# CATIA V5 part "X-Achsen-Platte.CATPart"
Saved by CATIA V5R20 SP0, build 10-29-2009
Part number: X-Achsen-Platte
Bounding box of the stored display mesh (mm): x -35 to 155, y -1 to 241, z 0 to 6
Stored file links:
  C:\Users\Andi\Desktop\Plasma\X-Achsen-Platte.CATPart
  C:\Program Files\Dassault Systemes\B20\win_b64\reffiles\standard\MetricThickPitch.txt
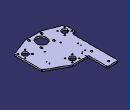
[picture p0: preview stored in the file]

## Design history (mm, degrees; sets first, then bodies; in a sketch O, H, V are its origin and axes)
Body1 (main body)
  Sketch1 on xy-plane, origin (0, 0, 0), H (1, 0, 0), V (0, 1, 0)
    construction circle A1 centre (-15, 44) radius 24
    point P1 (-15, 44)
    construction circle A2 centre (-15, 44) radius 19.95
    construction circle A3 centre (135, 44) radius 19.95
    point P2 (135, 44)
    construction circle A4 centre (135, 44) radius 24
    construction line L1 (-20, 136) -> (20, 136)
    construction line L2 (20, 136) -> (20, 241)
    construction line L3 (26.8489, 241) -> (-20, 241)
    construction line L4 (-20, 241) -> (-20, 136)
    point P5 (20, 241)
    line L5 (154.4846, 127.8747) -> (80.4846, 168.8747)
    line L6 (-20, 74) -> (-20, 238)
    circle A5 centre (0, 226) radius 4.1
    point P7 (0, 226)
    circle A6 centre (0, 161) radius 4.1
    point P8 (0, 161)
    circle A7 centre (-15, 44) radius 11
    circle A8 centre (135, 44) radius 11
    line L7 (-34.3676, 24.07) -> (28.1618, -0.6498)
    line L8 (17, 241) -> (-17, 241)
    circle A9 centre (60, 148) radius 11
    point P9 (60, 148)
    construction circle A10 centre (60, 148) radius 19.95
    construction circle A11 centre (60, 148) radius 24
    arc A12 centre (-17, 238) radius 3 from (-20, 238) to (-17, 241) cw
    construction line L9 (31, 62) -> (89, 62)
    construction line L10 (89, 62) -> (89, 0)
    construction line L11 (89, 0) -> (31, 0)
    construction line L12 (31, 0) -> (31, 62)
    construction line L13 (60, 29) -> (60, 33)
    point P17 (60, 29)
    point P18 (60, 33)
    line L14 (40.9, 29) -> (40.9, 33)
    line L15 (79.1, 33) -> (79.1, 29)
    arc A13 centre (60, 33) radius 19.1 from (40.9, 33) to (79.1, 33) cw
    arc A14 centre (60, 29) radius 19.1 from (79.1, 29) to (40.9, 29) cw
    construction line L16 (60, 148) -> (60, -15.4026)
    construction line L17 (-35.7345, 68) -> (137.8974, 68)
    construction line L18 (26.7433, 124) -> (71.6496, 124)
    point P27 (71.6496, 124)
    line L19 (91.8382, -0.6498) -> (154.3676, 24.07)
    line L20 (30, -1) -> (90, -1)
    arc A15 centre (30, 4) radius 5 from (30, -1) to (28.1618, -0.6498) cw
    point P30 (30, 4)
    arc A16 centre (90, 4) radius 5 from (91.8382, -0.6498) to (90, -1) cw
    point P33 (90, 4)
    arc A17 centre (-30, 74) radius 10 from (-20, 74) to (-30, 64) cw
    point P36 (26.8489, 241)
    line L21 (155, 127) -> (155, 25)
    line L22 (-35, 25) -> (-35, 63)
    line L23 (-34, 64) -> (-30, 64)
    arc A18 centre (-34, 63) radius 1 from (-35, 63) to (-34, 64) cw
    point P40 (-34, 63)
    arc A19 centre (-34, 25) radius 1 from (-34.3676, 24.07) to (-35, 25) cw
    point P43 (-34, 25)
    arc A20 centre (154, 25) radius 1 from (154.3676, 24.07) to (155, 25) ccw
    arc A21 centre (154, 127) radius 1 from (154.4846, 127.8747) to (155, 127) cw
    point P49 (154, 127)
    construction line L24 (80, 168) -> (80, 128)
    construction line L25 (80, 128) -> (40, 128)
    construction line L26 (40, 128) -> (40, 168)
    line L27 (20, 238) -> (20, 172)
    arc A22 centre (17, 238) radius 3 from (17, 241) to (20, 238) cw
    construction line L28 (40, 168) -> (80, 168)
    line L29 (80, 169) -> (23, 169)
    arc A23 centre (23, 172) radius 3 from (20, 172) to (23, 169) ccw
    arc A24 centre (80, 168) radius 1 from (80.4846, 168.8747) to (80, 169) ccw
    point P62 (80, 168)
    radius A2 = 19.95
    radius A1 = 24
    radius A5 = 4.1
    radius A6 = 4.1
    distance P8 L1 = 25
    radius A7 = 11
    radius A8 = 11 {= Sketch1.radius(A7)}
    distance P2 P1 = 150
    distance P7 L8 = 15
    radius A9 = 11 {= Sketch1.radius(A7)}
    radius A10 = 19.95 {= Sketch1.radius(A2)}
    radius A11 = 24 {= Sketch1.radius(A1)}
    length L2 = 105
    radius A12 = 3
    distance L9 L11 = 62
    distance L10 L12 = 58
    distance L13 L14 = 19.1
    distance P17 L11 = 29
    distance P18 L9 = 29 {= Sketch1.distance(P17 L11)}
    distance P27 L17 = 56
    distance L17 L9 = 6
    radius A15 = 5
    distance P33 P30 = 60
    distance L16 V = 60
    radius A17 = 10
    distance L11 L20 = 1
    distance L2 L6 = 40
    distance L22 P1 = 20
    radius A18 = 1
    radius A19 = 1 {= Sketch1.radius(A18)}
    distance L23 P1 = 20
    radius A20 = 1 {= Sketch1.radius(A18)}
    distance P40 P43 = 38
    distance L24 L26 = 40
    radius A22 = 3 {= Sketch1.radius(A12)}
    distance L1 L18 = 12
    distance L25 L28 = 40
    radius A23 = 3
    radius A24 = 1
    distance P62 L27 = 60
    radius A21 = 1
    distance P49 L20 = 128
    angle L5 L21 = 61.0112 (reference)
    distance L29 P9 = 21
    horizontal: L1 H, L3 H, L8 H, L9 H, L11 H, L17 H, L18 H, L23 H, L25 H, L28 H, L29 H
    vertical: L2 V, L4 V, L10 V, L12 V, L13 V, L16 V, L6 V, L21 V, L22 V, L24 V, L26 V, L27 V
    symmetry: L4 L2 V, L12 L10 L13, A2 A3 L16, A4 A1 L16, A16 A15 L16, L7 L19 L16, L21 L22 L16
    coincidence: P7 V, P8 V, L8 L3, L16 L13, L6 L4, L3 P5, L11 H, L8 P36, L2 L27
    tangency: A12 L8, A12 L6, A13 L14, A14 L14, A13 L15, A14 L15, A15 L20, A15 L7, A16 L19, A16 L20, A17 L6, L17 A4, L18 A11, A17 L23, A18 L22, A18 L23, A19 L7, A19 L22, A20 L19, A20 L21, A21 L5, A21 L21, A22 L8, A22 L27, A23 L27, A23 L29, A24 L5, A24 L29
    equidistance: L24 L26 P9, L28 L25 P9
  Pad1: profile Sketch1, direction (0, 0, 1), length 6
  Sketch2 on end face of Pad1, origin (0, 0, 6), H (1, 0, 0), V (0, 1, 0)
    construction line L1 (36.43, 56.57) -> (36.43, 52.57)
    point P1 (36.43, 56.57)
    line L2 (39.53, 56.57) -> (39.53, 52.57)
    line L3 (33.33, 52.57) -> (33.33, 56.57)
    arc A1 centre (36.43, 52.57) radius 3.1 from (39.53, 52.57) to (33.33, 52.57) cw
    arc A2 centre (36.43, 56.57) radius 3.1 from (33.33, 56.57) to (39.53, 56.57) cw
    construction line L4 (60, 33) -> (60, 47.1247)
    point P7 (60, 33)
    construction line L5 (60, 33) -> (69.7993, 33)
    reference projected point E1 (60, 33) from axis of face of Pad1 from Sketch1.A13
    distance L1 L2 = 3.1
    distance L1 L4 = 23.57
    distance P1 L5 = 23.57 {= Sketch2.distance(L1 L4)}
    length L1 = 4
    vertical: L1 V, L4 V
    tangency: A1 L2, A2 L2, A1 L3, A2 L3
    horizontal: L5 H
    coincidence: E1 P7
  Pocket1: profile Sketch2, direction (0, 0, -1), through (limit type 6)
  RectPattern1: of Pocket1, direction 1 instances 2, spacing 47.14, along end face of Pad1, direction 2 instances 2, spacing 47.14, along end face of Pad1 reversed
  Sketch3 on end face of Pad1, origin (24.1794, 177.194, 6), H (1, 0, 0), V (0, 1, 0)
    point P1 (1.3206, -13.194)
    construction line L1 (-3.6794, -8.194) -> (14.3206, -8.194)
    construction line L2 (14.3206, -8.194) -> (14.3206, -32.194)
    construction line L3 (14.3206, -32.194) -> (-3.6794, -32.194)
    construction line L4 (-3.6794, -32.194) -> (-3.6794, -8.194)
    point P6 (5.3206, -8.194)
    point P7 (5.3206, -32.194)
    reference intersected line E1 (-4.1794, 15.806) -> (-4.1794, 11.806) from face of Pad1 from Sketch1.L27
    reference projected line E2 (55.8206, -8.194) -> (-1.1794, -8.194) from edge [face of Pad1 from Sketch1.L29 | end face of Pad1]
    distance L4 L2 = 18
    distance L1 L3 = 24
    distance E1 L4 = 0.5
    distance L1 P1 = 5
    distance L4 P1 = 5
    horizontal: L1 H, L3 H
    vertical: L2 V, L4 V
    midpoint: P6 L1, P7 L3
    coincidence: L1 E2
  Hole1: placed by Sketch3, at (25.5, 164, 6) direction (0, 0, -1), diameter 3.242, through (limit type 6), threaded "M4", thread diameter 4, thread depth 6, pitch 0.7
  RectPattern2: of Hole1, direction 1 instances 1, spacing 18, along end face of Pad1, direction 2 instances 2, spacing 14, along end face of Pad1 reversed
  Sketch4 on end face of Pad1, origin (1.5446, 74.0443, 6), H (1, 0, 0), V (0, 1, 0)
    point P1 (28.4554, -0.0443)
    construction circle A1 centre (28.4554, -0.0443) radius 8
    construction line L1 (58.4554, -45.0443) -> (58.4554, -1.904)
    point P2 (58.4554, -45.0443)
    construction line L2 (58.4554, -45.0443) -> (73.3755, -45.0443)
    reference projected point E1 (58.4554, -45.0443) from axis of face of Pad1 from Sketch1.A14
    radius A1 = 8
    distance L2 P1 = 45
    distance P1 L1 = 30
    vertical: L1 V
    horizontal: L2 H
    coincidence: P2 E1
  Hole2: placed by Sketch4, at (30, 74, 6) direction (0, 0, -1), diameter 4.917, through (limit type 6), threaded "M6", thread diameter 6, thread depth 6, pitch 1
  RectPattern3: of Hole2, direction 1 instances 2, spacing 60, along end face of Pad1
  Sketch5 on end face of Pad1, origin (119.6881, 121.4363, 6), H (1, 0, 0), V (0, 1, 0)
    point P1 (0.3119, -0.4363)
    reference intersected line E1 through (-119.6881, 0) direction (0, 1) from yz-plane
    reference intersected line E2 through (0, -121.4363) direction (-1, 0) from zx-plane
    distance E1 P1 = 120
    distance E2 P1 = 121
  Hole3: placed by Sketch5, at (120, 121, 6) direction (0, 0, -1), diameter 3.242, through (limit type 6), threaded "M4", thread diameter 4, thread depth 6, pitch 0.7
  RectPattern4: of Hole3, direction 1 instances 2, spacing 120, along end face of Pad1 reversed, direction 2 instances 2, spacing 11, along end face of Pad1 reversed
  Sketch6 on end face of Pad1, origin (47.8438, 172.6617, 6), H (1, 0, 0), V (0, 1, 0)
    point P1 (-27.8438, -26.6617)
    reference intersected line E1 through (-47.8438, 0) direction (0, 1) from yz-plane
    reference intersected line E2 through (0, -172.6617) direction (-1, 0) from zx-plane
    distance P1 E1 = 20
    distance E2 P1 = 146
  Hole4: placed by Sketch6, at (20, 146, 6) direction (0, 0, -1), diameter 3.242, through (limit type 6), threaded "M4", thread diameter 4, thread depth 6, pitch 0.7
  RectPattern5: of Hole4, direction 1 instances 2, spacing 11, along end face of Pad1 reversed
  Sketch7 on end face of Pad1, origin (-27.3993, 60.8733, 6), H (1, 0, 0), V (0, 1, 0)
    point P1 (-1.1007, -3.3733)
    construction line L1 (12.3993, -16.8733) -> (20.1667, -16.8733)
    point P2 (12.3993, -16.8733)
    construction line L2 (12.3993, -16.8733) -> (12.3993, -8.4046)
    reference projected point E1 (12.3993, -16.8733) from axis of face of Pad1 from Sketch1.A7
    distance L1 P1 = 13.5
    distance L2 P1 = 13.5 {= Sketch7.distance(L1 P1)}
    horizontal: L1 H
    vertical: L2 V
    coincidence: P2 E1
  Hole5: placed by Sketch7, at (-28.5, 57.5, 6) direction (0, 0, -1), diameter 5.5, through (limit type 6)
  CircPattern1: of Hole5, instances 4, angular step 90 {= 360.0*1 deg/CircPattern1.AngularNumber}, axis from face of Pad1 from Sketch1.A7
  Sketch8 on end face of Pad1, origin (91.0521, 56.2744, 6), H (1, 0, 0), V (0, 1, 0)
    point P1 (30.4479, 1.2256)
    construction line L1 (43.9479, -12.2744) -> (55.6902, -12.2744)
    point P2 (43.9479, -12.2744)
    construction line L2 (43.9479, -12.2744) -> (43.9479, -4.3575)
    reference projected point E1 (43.9479, -12.2744) from axis of face of Pad1 from Sketch1.A8
    distance L1 P1 = 13.5 {= Sketch8.distance(P1 L2)}
    distance P1 L2 = 13.5 {= Sketch7.distance(L1 P1)}
    horizontal: L1 H
    vertical: L2 V
    coincidence: P2 E1
  Hole6: placed by Sketch8, at (121.5, 57.5, 6) direction (0, 0, -1), diameter 5.5 {= Hole5.Diameter}, through (limit type 6)
  CircPattern2: of Hole6, instances 4, angular step 90 {= 360.0*1 deg/CircPattern2.AngularNumber}, axis from face of Pad1 from Sketch1.A8
  Sketch9 on end face of Pad1, origin (27.6845, 164.219, 6), H (1, 0, 0), V (0, 1, 0)
    point P1 (18.8155, -2.719)
    construction line L1 (32.3155, -16.219) -> (47.5995, -16.219)
    point P2 (32.3155, -16.219)
    construction line L2 (32.3155, -16.219) -> (32.3155, -4.9243)
    reference projected point E1 (32.3155, -16.219) from axis of face of Pad1 from Sketch1.A9
    distance P1 L2 = 13.5 {= Sketch7.distance(L1 P1)}
    distance L1 P1 = 13.5 {= Sketch9.distance(P1 L2)}
    horizontal: L1 H
    vertical: L2 V
    coincidence: P2 E1
  Hole7: placed by Sketch9, at (46.5, 161.5, 6) direction (0, 0, -1), diameter 5.5 {= Hole5.Diameter}, through (limit type 6)
  CircPattern3: of Hole7, instances 4, angular step 90 {= 360.0*1 deg/CircPattern3.AngularNumber}, axis from face of Pad1 from Sketch1.A9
